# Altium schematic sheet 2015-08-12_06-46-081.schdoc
size 557 x 193 mm; SheetNumber: 1; SheetTotal: 1
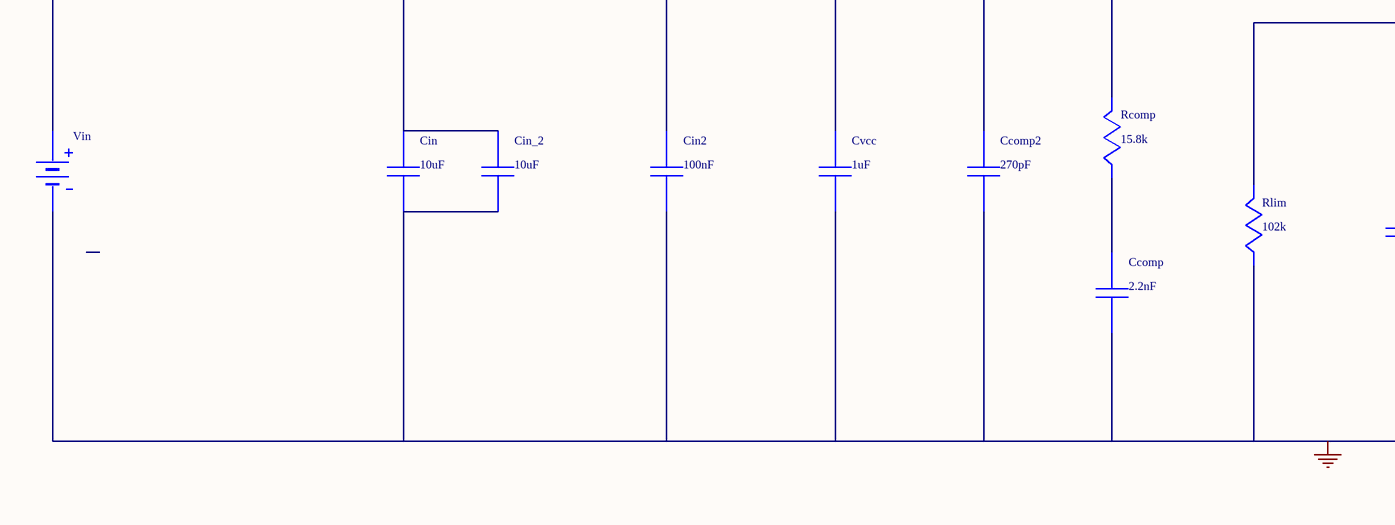
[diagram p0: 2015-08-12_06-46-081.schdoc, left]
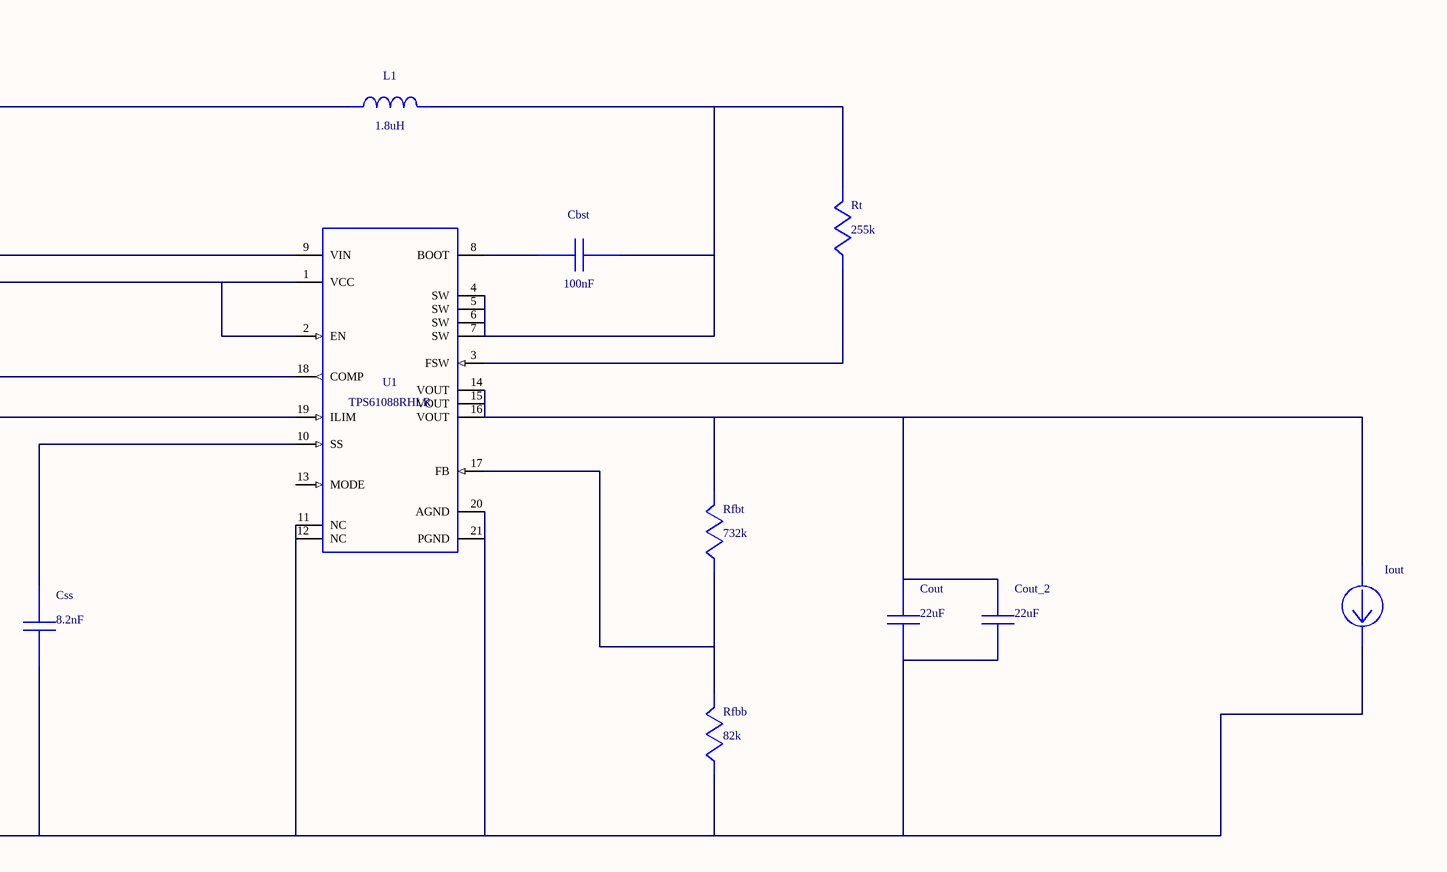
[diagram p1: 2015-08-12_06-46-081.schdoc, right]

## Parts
Cbst  value 100nF  (hidden comment: C1005X5R1A104K)
Ccomp  value 2.2nF  (hidden comment: CC0805KRX7R9BB222)
Ccomp2  value 270pF  (hidden comment: C2012C0G1H271J)
Cin  value 10uF  (hidden comment: GRM21BR61A106KE19L)
Cin2  value 100nF  (hidden comment: GRM155R61A104KA01D)
Cin_2  value 10uF  (hidden comment: GRM21BR61A106KE19L)
Cout  value 22uF  (hidden comment: GRM32ER61E226KE15L)
Cout_2  value 22uF  (hidden comment: GRM32ER61E226KE15L)
Css  value 8.2nF  (hidden comment: GRM155R71C822KA01D)
Cvcc  value 1uF  (hidden comment: C1608X5R1A105K)
Iout  WB_CURRENT_LOAD  (value not drawn)
L1  value 1.8uH  (hidden comment: SDR2207-1R8ML)
Rcomp  value 15.8k  (hidden comment: CRCW040215K8FKED)
Rfbb  value 82k  (hidden comment: RR1220P-823-D)
Rfbt  value 732k  (hidden comment: CRCW0402732KFKED)
Rlim  value 102k  (hidden comment: ERJ-8ENF1023V)
Rt  value 255k  (hidden comment: ERJ-8ENF2553V)
U1  TPS61088RHLR
Vin  WB_BATTERY  (value not drawn)

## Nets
0: Ccomp.2 Ccomp2.2 Cin.2 Cin2.2 Cin_2.2 Cout.2 Cout_2.2 Css.2 Cvcc.2 Iout.2(-) Rfbb.2 Rlim.2 U1.11(NC) U1.12(NC) U1.20(AGND) U1.21(PGND) Vin.2(-)
NetCbst_1: Cbst.1 U1.8(BOOT)
NetCbst_2: Cbst.2 L1.2 Rt.1 U1.4(SW) U1.5(SW) U1.6(SW) U1.7(SW)
NetCcomp2_1: Ccomp2.1 Rcomp.1 U1.18(COMP)
NetCcomp_1: Ccomp.1 Rcomp.2
NetCin_1: Cin.1 Cin2.1 Cin_2.1 L1.1 U1.9(VIN) Vin.1(+)
NetCout_1: Cout.1 Cout_2.1 Iout.1(+) Rfbt.1 U1.14(VOUT) U1.15(VOUT) U1.16(VOUT)
NetCss_1: Css.1 U1.10(SS)
NetCvcc_1: Cvcc.1 U1.1(VCC) U1.2(EN)
NetRfbb_1: Rfbb.1 Rfbt.2 U1.17(FB)
NetRlim_1: Rlim.1 U1.19(ILIM)
NetRt_2: Rt.2 U1.3(FSW)

Not connected (* = marked no-connect by the designer): U1 13(MODE)

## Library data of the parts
Cbst = C1005X5R1A104K: Manufacturer Name: TDK
Ccomp = CC0805KRX7R9BB222: CC0805KRX7R9BB22; Manufacturer Name: Yageo America
Ccomp2 = C2012C0G1H271J: Manufacturer Name: TDK
Cin Cin_2 = GRM21BR61A106KE19L: GRM21BR61A106KE1; Manufacturer Name: MuRata
Cin2 = GRM155R61A104KA01D: GRM155R61A104KA0; Manufacturer Name: MuRata
Cout Cout_2 = GRM32ER61E226KE15L: GRM32ER61E226KE1; Manufacturer Name: MuRata
Css = GRM155R71C822KA01D: GRM155R71C822KA0; Manufacturer Name: MuRata
Cvcc = C1608X5R1A105K: Manufacturer Name: TDK
Iout = WB_CURRENT_LOAD: Value: UNLISTED
L1 = SDR2207-1R8ML: Manufacturer Name: Bourns
Rcomp = CRCW040215K8FKED: Manufacturer Name: Vishay-Dale
Rfbb = RR1220P-823-D: Manufacturer Name: Susumu Co Ltd
Rfbt = CRCW0402732KFKED: Manufacturer Name: Vishay-Dale
Rlim = ERJ-8ENF1023V: Manufacturer Name: Panasonic
Rt = ERJ-8ENF2553V: Manufacturer Name: Panasonic
U1 = TPS61088RHLR: Manufacturer Name: Texas Instruments; Value: UNLISTED
Vin = WB_BATTERY: Value: UNLISTED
